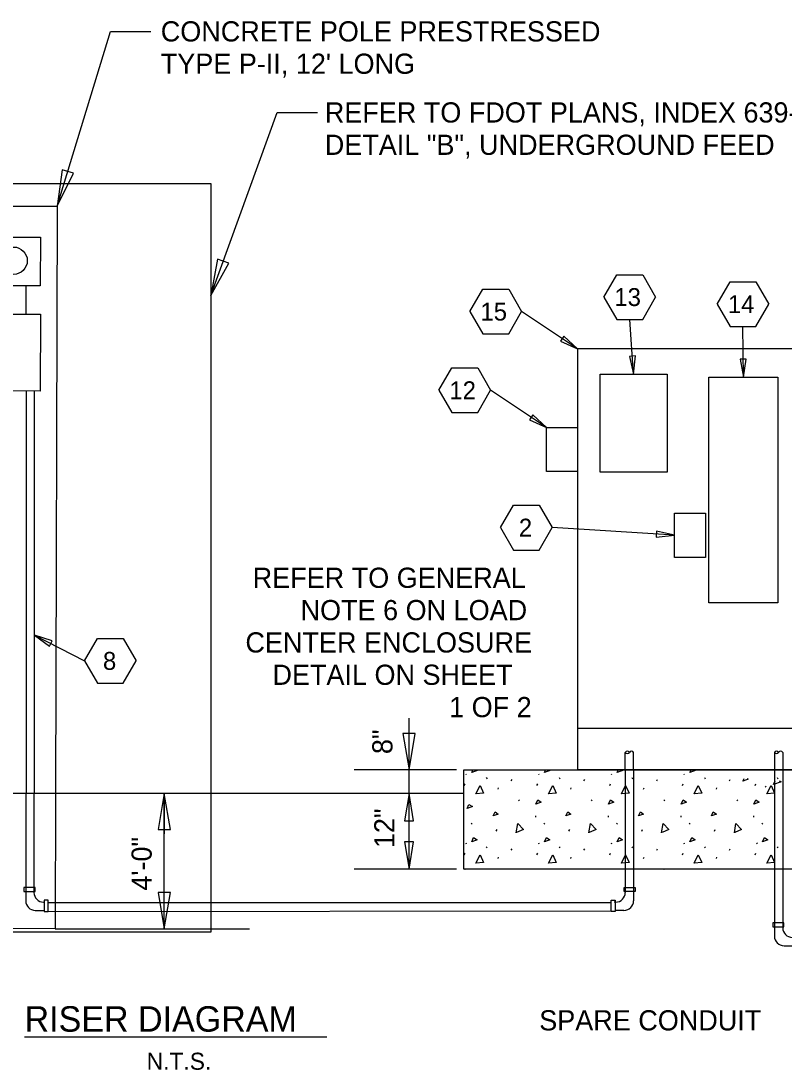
# Model space of a CAD drawing. Extents: x 359576 to 360896, y 1607020 to 1607868.
# Drawn here: x 360503.5 to 360730.2, y 1607389.8 to 1607701.3 of the extents above; entities that cross this region are included whole.
import ezdxf

# ---------------------------------------------------------------- set-up
doc = ezdxf.new("R2010")
doc.units = 0
doc.layers.add('Default', color=7, linetype='Continuous')
doc.layers.add('LaneLine_ep', color=7, linetype='Continuous')

msp = doc.modelspace()

# ---------------------------------------------------------------- linework, layer by layer
at = {"layer": 'Default'}
for p, q in [((360489.42, 1607646.37), (360514.17, 1607646.3)), ((360514.24, 1607646.3), (360513.74, 1607471.93)), ((360676.67, 1607619.32), (360680.5, 1607625.95)), ((360680.5, 1607625.95), (360688.17, 1607625.95)), ((360688.17, 1607625.95), (360692, 1607619.32)), ((360505.03, 1607614.28), (360505.03, 1607622.63)), ((360636.85, 1607615), (360640.68, 1607621.64)), ((360640.68, 1607621.64), (360648.35, 1607621.64)), ((360648.35, 1607621.64), (360652.18, 1607615)), ((360710.28, 1607617.2), (360714.12, 1607623.84)), ((360714.12, 1607623.84), (360721.78, 1607623.84)), ((360721.78, 1607623.84), (360725.62, 1607617.2)), ((360676.67, 1607619.32), (360680.5, 1607612.68)), ((360688.17, 1607612.68), (360692, 1607619.32)), ((360636.85, 1607615), (360640.68, 1607608.36)), ((360648.35, 1607608.36), (360652.18, 1607615)), ((360710.28, 1607617.2), (360714.12, 1607610.56)), ((360721.78, 1607610.56), (360725.62, 1607617.2)), ((360680.5, 1607612.68), (360688.17, 1607612.68)), ((360640.68, 1607608.36), (360648.35, 1607608.36)), ((360714.12, 1607610.56), (360721.78, 1607610.56)), ((360627.65, 1607591.64), (360631.48, 1607598.28)), ((360631.48, 1607598.28), (360639.15, 1607598.28)), ((360639.15, 1607598.28), (360642.98, 1607591.64)), ((360504.95, 1607591.34), (360504.95, 1607471.95)), ((360507.41, 1607591.41), (360507.41, 1607471.95)), ((360627.65, 1607591.64), (360631.48, 1607585)), ((360639.15, 1607585), (360642.98, 1607591.64)), ((360631.48, 1607585), (360639.15, 1607585)), ((360645.91, 1607550.85), (360649.74, 1607557.49)), ((360649.74, 1607557.49), (360657.41, 1607557.49)), ((360657.41, 1607557.49), (360661.24, 1607550.85)), ((360645.91, 1607550.85), (360649.74, 1607544.21)), ((360657.41, 1607544.21), (360661.24, 1607550.85)), ((360649.74, 1607544.21), (360657.41, 1607544.21)), ((360522.32, 1607511.27), (360526.16, 1607517.91)), ((360526.16, 1607517.91), (360533.82, 1607517.91)), ((360533.82, 1607517.91), (360537.65, 1607511.27)), ((360522.32, 1607511.27), (360526.16, 1607504.63)), ((360533.82, 1607504.63), (360537.65, 1607511.27)), ((360526.16, 1607504.63), (360533.82, 1607504.63)), ((360668.76, 1607491.27), (360773.13, 1607491.27)), ((360682.99, 1607479), (360682.99, 1607484.1)), ((360685.45, 1607478.99), (360685.45, 1607484.1)), ((360727.31, 1607484.1), (360727.31, 1607429.57)), ((360729.77, 1607484.1), (360729.77, 1607432.03)), ((360635.06, 1607449.39), (360635.06, 1607478.91)), ((360635.06, 1607478.91), (360795.13, 1607478.91)), ((360635.61, 1607477.79), (360635.72, 1607477.56)), ((360657.21, 1607477.79), (360657.32, 1607477.56)), ((360678.81, 1607477.79), (360678.93, 1607477.56)), ((360682.99, 1607479), (360682.99, 1607442.5)), ((360685.45, 1607478.99), (360685.45, 1607440.04)), ((360700.41, 1607477.79), (360700.53, 1607477.56)), ((360635.15, 1607474.31), (360635.38, 1607474.77)), ((360641.7, 1607476.65), (360641.93, 1607476.31)), ((360649.11, 1607475.62), (360649.34, 1607476.08)), ((360656.75, 1607474.31), (360656.98, 1607474.77)), ((360663.31, 1607476.65), (360663.54, 1607476.31)), ((360670.72, 1607475.62), (360670.95, 1607476.08)), ((360678.36, 1607474.31), (360678.58, 1607474.77)), ((360684.91, 1607476.65), (360685.14, 1607476.31)), ((360692.32, 1607475.62), (360692.55, 1607476.08)), ((360699.96, 1607474.31), (360700.19, 1607474.77)), ((360706.51, 1607476.65), (360706.74, 1607476.31)), ((360713.92, 1607475.62), (360714.15, 1607476.08)), ((360721.56, 1607474.31), (360721.79, 1607474.77)), ((360728.12, 1607476.65), (360728.34, 1607476.31)), ((360635.06, 1607471.95), (360329.76, 1607471.95)), ((360504.86, 1607471.95), (360504.86, 1607440.04)), ((360507.32, 1607471.95), (360507.32, 1607442.5)), ((360645.24, 1607473.17), (360645.35, 1607473.63)), ((360666.84, 1607473.17), (360666.96, 1607473.63)), ((360688.44, 1607473.17), (360688.56, 1607473.63)), ((360710.05, 1607473.17), (360710.16, 1607473.63)), ((360724.57, 1607474.12), (360724.73, 1607473.8)), ((360651.28, 1607469.98), (360651.51, 1607469.75)), ((360672.88, 1607469.98), (360673.11, 1607469.75)), ((360694.49, 1607469.98), (360694.71, 1607469.75)), ((360716.09, 1607469.98), (360716.32, 1607469.75)), ((360656.3, 1607465.31), (360656.3, 1607464.85)), ((360677.9, 1607465.31), (360677.9, 1607464.85)), ((360699.5, 1607465.31), (360699.5, 1607464.85)), ((360721.11, 1607465.31), (360721.11, 1607464.85)), ((360637.26, 1607462.8), (360637.49, 1607463.14)), ((360658.86, 1607462.8), (360659.09, 1607463.14)), ((360680.46, 1607462.8), (360680.69, 1607463.14)), ((360702.07, 1607462.8), (360702.3, 1607463.14)), ((360723.67, 1607462.8), (360723.9, 1607463.14)), ((360644.67, 1607460.75), (360644.9, 1607461.2)), ((360666.27, 1607460.75), (360666.5, 1607461.2)), ((360687.87, 1607460.75), (360688.1, 1607461.2)), ((360709.48, 1607460.75), (360709.71, 1607461.2)), ((360635.61, 1607457.21), (360635.72, 1607456.98)), ((360641.7, 1607456.07), (360641.93, 1607455.73)), ((360657.21, 1607457.21), (360657.32, 1607456.98)), ((360663.31, 1607456.07), (360663.54, 1607455.73)), ((360678.81, 1607457.21), (360678.93, 1607456.98)), ((360684.91, 1607456.07), (360685.14, 1607455.73)), ((360700.41, 1607457.21), (360700.53, 1607456.98)), ((360706.51, 1607456.07), (360706.74, 1607455.73)), ((360722.02, 1607457.21), (360722.13, 1607456.98)), ((360728.12, 1607456.07), (360728.34, 1607455.73)), ((360635.15, 1607453.73), (360635.38, 1607454.19)), ((360645.24, 1607452.59), (360645.35, 1607453.05)), ((360649.11, 1607455.05), (360649.34, 1607455.5)), ((360656.75, 1607453.73), (360656.98, 1607454.19)), ((360666.84, 1607452.59), (360666.96, 1607453.05)), ((360670.72, 1607455.05), (360670.95, 1607455.5)), ((360678.36, 1607453.73), (360678.58, 1607454.19)), ((360688.44, 1607452.59), (360688.56, 1607453.05)), ((360692.32, 1607455.05), (360692.55, 1607455.5)), ((360699.96, 1607453.73), (360700.19, 1607454.19)), ((360710.05, 1607452.59), (360710.16, 1607453.05)), ((360713.92, 1607455.05), (360714.15, 1607455.5)), ((360721.56, 1607453.73), (360721.79, 1607454.19)), ((360795.13, 1607449.39), (360635.06, 1607449.39)), ((360651.28, 1607449.4), (360651.29, 1607449.39)), ((360672.88, 1607449.4), (360672.89, 1607449.39)), ((360694.49, 1607449.4), (360694.5, 1607449.39)), ((360716.09, 1607449.4), (360716.1, 1607449.39)), ((360507.71, 1607437.19), (360510.32, 1607437.19)), ((360511.49, 1607439.51), (360678.83, 1607439.51)), ((360511.49, 1607436.9), (360678.83, 1607437.04)), ((360680.14, 1607439.65), (360679.72, 1607439.65)), ((360682.6, 1607437.19), (360679.99, 1607437.19)), ((360730.16, 1607426.72), (360732.77, 1607426.72)), ((360504.52, 1607399.66), (360594.31, 1607399.66))]:
    msp.add_line(p, q, dxfattribs=at)
for points in [[(360448.79, 1607653.09), (360559.9, 1607653.09), (360559.9, 1607430.72), (360448.79, 1607430.72)], [(360493.19, 1607637.12), (360509.24, 1607637.07), (360509.2, 1607622.62), (360493.15, 1607622.67)], [(360493.19, 1607614.29), (360509.24, 1607614.24), (360509.18, 1607591.41), (360493.13, 1607591.45)], [(360773.13, 1607603.99), (360668.76, 1607603.99), (360668.76, 1607478.99), (360773.13, 1607478.99)], [(360675.54, 1607596.4), (360695.42, 1607596.4), (360695.42, 1607567.32), (360675.54, 1607567.32)], [(360707.8, 1607595.52), (360728.36, 1607595.52), (360728.36, 1607528.53), (360707.8, 1607528.53)], [(360668.76, 1607580.63), (360668.76, 1607567.51), (360659.56, 1607567.51), (360659.56, 1607580.63)], [(360706.82, 1607555.15), (360706.82, 1607542.03), (360697.62, 1607542.03), (360697.62, 1607555.15)], [(360507.69, 1607442.82), (360507.69, 1607443.99), (360504.34, 1607443.99), (360504.34, 1607442.82)], [(360682.62, 1607442.82), (360682.62, 1607443.99), (360685.97, 1607443.99), (360685.97, 1607442.82)], [(360511.49, 1607440.24), (360510.32, 1607440.24), (360510.32, 1607436.9), (360511.49, 1607436.9)], [(360678.83, 1607440.24), (360679.99, 1607440.24), (360679.99, 1607436.9), (360678.83, 1607436.9)], [(360730.14, 1607432.35), (360730.14, 1607433.52), (360726.79, 1607433.52), (360726.79, 1607432.35)]]:
    msp.add_lwpolyline(points, close=True, dxfattribs=at)
for points in [[(360638.66, 1607478.91), (360638.97, 1607478.7), (360637.37, 1607478.13)], [(360637.37, 1607478.13), (360637.73, 1607478.91)], [(360660.26, 1607478.91), (360660.57, 1607478.7), (360658.98, 1607478.13)], [(360658.98, 1607478.13), (360659.33, 1607478.91)], [(360681.86, 1607478.91), (360682.17, 1607478.7), (360680.58, 1607478.13)], [(360680.58, 1607478.13), (360680.93, 1607478.91)], [(360703.47, 1607478.91), (360703.78, 1607478.7), (360702.18, 1607478.13)], [(360702.18, 1607478.13), (360702.53, 1607478.91)], [(360719.23, 1607476.35), (360719.54, 1607476.15), (360717.95, 1607475.58)], [(360717.95, 1607475.58), (360718.3, 1607476.35)], [(360728.84, 1607475.69), (360729.28, 1607475.4), (360727.04, 1607474.6)], [(360727.04, 1607474.6), (360727.54, 1607475.69)], [(360513.74, 1607471.93), (360513.62, 1607431.72), (360488.88, 1607431.79), (360489, 1607471.96)], [(360638.63, 1607471.8), (360639.88, 1607474.31), (360640.91, 1607472.03), (360638.63, 1607471.8)], [(360660.23, 1607471.8), (360661.48, 1607474.31), (360662.51, 1607472.03), (360660.23, 1607471.8)], [(360681.83, 1607471.8), (360683.09, 1607474.31), (360684.11, 1607472.03), (360681.83, 1607471.8)], [(360703.44, 1607471.8), (360704.69, 1607474.31), (360705.72, 1607472.03), (360703.44, 1607471.8)], [(360725.04, 1607471.8), (360726.29, 1607474.31), (360727.32, 1607472.03), (360725.04, 1607471.8)], [(360635.98, 1607467.44), (360636.55, 1607468.69), (360637.57, 1607468.01), (360635.98, 1607467.44)], [(360656.41, 1607468.73), (360656.98, 1607469.98), (360658.01, 1607469.3), (360656.41, 1607468.73)], [(360678.01, 1607468.73), (360678.58, 1607469.98), (360679.61, 1607469.3), (360678.01, 1607468.73)], [(360699.62, 1607468.73), (360700.19, 1607469.98), (360701.21, 1607469.3), (360699.62, 1607468.73)], [(360721.22, 1607468.73), (360721.79, 1607469.98), (360722.82, 1607469.3), (360721.22, 1607468.73)], [(360643.76, 1607465.31), (360644.33, 1607466.45), (360645.24, 1607465.76), (360643.76, 1607465.31)], [(360665.36, 1607465.31), (360665.93, 1607466.45), (360666.84, 1607465.76), (360665.36, 1607465.31)], [(360686.96, 1607465.31), (360687.53, 1607466.45), (360688.44, 1607465.76), (360686.96, 1607465.31)], [(360708.57, 1607465.31), (360709.14, 1607466.45), (360710.05, 1607465.76), (360708.57, 1607465.31)], [(360650.6, 1607460.18), (360651.05, 1607463.03), (360652.76, 1607461.2), (360650.71, 1607460.29)], [(360672.2, 1607460.18), (360672.66, 1607463.03), (360674.37, 1607461.2), (360672.31, 1607460.29)], [(360693.8, 1607460.18), (360694.26, 1607463.03), (360695.97, 1607461.2), (360693.92, 1607460.29)], [(360715.41, 1607460.18), (360715.86, 1607463.03), (360717.57, 1607461.2), (360715.52, 1607460.29)], [(360637.37, 1607457.55), (360637.94, 1607458.81), (360638.97, 1607458.12), (360637.37, 1607457.55)], [(360658.98, 1607457.55), (360659.55, 1607458.81), (360660.57, 1607458.12), (360658.98, 1607457.55)], [(360680.58, 1607457.55), (360681.15, 1607458.81), (360682.17, 1607458.12), (360680.58, 1607457.55)], [(360702.18, 1607457.55), (360702.75, 1607458.81), (360703.78, 1607458.12), (360702.18, 1607457.55)], [(360723.78, 1607457.55), (360724.35, 1607458.81), (360725.38, 1607458.12), (360723.78, 1607457.55)], [(360638.63, 1607451.23), (360639.88, 1607453.73), (360640.91, 1607451.45), (360638.63, 1607451.23)], [(360660.23, 1607451.23), (360661.48, 1607453.73), (360662.51, 1607451.45), (360660.23, 1607451.23)], [(360681.83, 1607451.23), (360683.09, 1607453.73), (360684.11, 1607451.45), (360681.83, 1607451.23)], [(360703.44, 1607451.23), (360704.69, 1607453.73), (360705.72, 1607451.45), (360703.44, 1607451.23)], [(360725.04, 1607451.23), (360726.29, 1607453.73), (360727.32, 1607451.45), (360725.04, 1607451.23)], [(360635.37, 1607449.39), (360635.38, 1607449.4), (360635.39, 1607449.39)], [(360656.98, 1607449.39), (360656.98, 1607449.4), (360656.99, 1607449.39)], [(360678.58, 1607449.39), (360678.58, 1607449.4), (360678.6, 1607449.39)], [(360700.18, 1607449.39), (360700.19, 1607449.4), (360700.2, 1607449.39)], [(360721.79, 1607449.39), (360721.79, 1607449.4), (360721.8, 1607449.39)]]:
    msp.add_lwpolyline(points, dxfattribs=at)
msp.add_circle((360501.27, 1607630.13), 4.06, dxfattribs=at)
for centre, radius, start, end in [((360683.61, 1607483.75), 0.708, 29.4643, 150.5357), ((360683.61, 1607484.45), 0.708, 209.4643, 330.5357), ((360684.84, 1607483.75), 0.708, 29.4643, 150.5357), ((360727.93, 1607483.75), 0.708, 29.4643, 150.5357), ((360727.93, 1607484.45), 0.708, 209.4643, 330.5357), ((360729.16, 1607483.75), 0.708, 29.4643, 150.5357), ((360510.17, 1607442.5), 2.85, 180, 270), ((360680.14, 1607442.5), 2.85, 270, 360), ((360507.71, 1607440.04), 2.85, 180, 270), ((360682.6, 1607440.04), 2.85, 270, 360), ((360732.62, 1607432.03), 2.85, 180, 270), ((360730.16, 1607429.57), 2.85, 180, 270)]:
    msp.add_arc(centre, radius, start, end, dxfattribs=at)
at = {"layer": 'LaneLine_ep'}
for p, q in [((360697.62, 1607548.59), (360661.24, 1607550.85)), ((360632.87, 1607478.91), (360602.43, 1607478.91)), ((360618.74, 1607471.95), (360618.74, 1607478.91)), ((360632.87, 1607449.39), (360602.43, 1607449.39)), ((360513.62, 1607431.72), (360549.46, 1607431.72)), ((360513.62, 1607431.72), (360571.39, 1607431.72)), ((360531.54, 1607431.72), (360550.97, 1607431.72))]:
    msp.add_line(p, q, dxfattribs=at)
for points in [[(360514.24, 1607646.3), (360530.07, 1607698.22), (360542.05, 1607698.22)], [(360559.87, 1607619.83), (360579.53, 1607674.15), (360591.51, 1607674.15)], [(360668.76, 1607603.99), (360652.18, 1607615)], [(360685.48, 1607596.4), (360684.34, 1607612.68)], [(360718.08, 1607595.52), (360717.95, 1607610.56)], [(360659.56, 1607580.63), (360642.98, 1607591.64)], [(360507.5, 1607518.88), (360522.32, 1607511.27)], [(360618.74, 1607478.91), (360618.74, 1607494.29)], [(360546.03, 1607431.72), (360546.03, 1607471.95)], [(360546.03, 1607471.95), (360546.03, 1607459.97)], [(360618.74, 1607449.39), (360618.74, 1607471.95)]]:
    msp.add_lwpolyline(points, dxfattribs=at)
for points in [[(360515.67, 1607657.14), (360514.24, 1607646.3), (360519.1, 1607656.09)], [(360561.85, 1607630.58), (360559.87, 1607619.83), (360565.23, 1607629.36)], [(360663.77, 1607606.23), (360668.76, 1607603.99), (360664.76, 1607607.73)], [(360684.21, 1607601.72), (360685.48, 1607596.4), (360686, 1607601.85)], [(360717.13, 1607600.91), (360718.08, 1607595.52), (360718.93, 1607600.93)], [(360654.56, 1607582.86), (360659.56, 1607580.63), (360655.56, 1607584.36)], [(360692.17, 1607548.03), (360697.62, 1607548.59), (360692.29, 1607549.83)], [(360512.72, 1607517.22), (360507.5, 1607518.88), (360511.89, 1607515.62)], [(360616.95, 1607489.69), (360618.74, 1607478.91), (360620.54, 1607489.69)], [(360547.83, 1607461.17), (360546.03, 1607471.95), (360544.23, 1607461.17)], [(360620.11, 1607463.76), (360618.74, 1607471.95), (360617.38, 1607463.76)], [(360617.38, 1607457.59), (360618.74, 1607449.39), (360620.11, 1607457.59)], [(360544.23, 1607442.5), (360546.03, 1607431.72), (360547.83, 1607442.5)]]:
    msp.add_lwpolyline(points, close=True, dxfattribs=at)

# ---------------------------------------------------------------- texts
at = {"layer": 'Default'}
for s, p in [('CONCRETE POLE PRESTRESSED', (360544.99, 1607695.22)), ("TYPE P-II, 12' LONG", (360544.99, 1607685.62)), ('REFER TO FDOT PLANS, INDEX 639-001', (360593.72, 1607671.15)), ('DETAIL "B", UNDERGROUND FEED', (360593.72, 1607661.55))]:
    msp.add_text(s, height=6, dxfattribs=at).set_placement(p)
for s, height, rotation, p in [('13', 5.311, 360, (360679.75, 1607616.67)), ('15', 5.311, 360, (360639.96, 1607612.35)), ('14', 5.311, 360, (360713.48, 1607614.55)), ('12', 5.311, 360, (360630.73, 1607588.99)), ('2', 5.31, 360, (360651.38, 1607548.2)), ('REFER TO GENERAL', 6, 0, (360572.29, 1607532.97)), ('NOTE 6 ON LOAD', 6, 0, (360586.52, 1607523.37)), ('CENTER ENCLOSURE', 6, 0, (360570.14, 1607513.77)), ('8', 5.31, 360, (360527.81, 1607508.63)), ('DETAIL ON SHEET', 6, 0, (360578.17, 1607504.17)), ('1 OF 2', 6, 0, (360630.66, 1607494.57)), ('8"', 5.99, 90, (360613.82, 1607483.62)), ('12"', 5.99, 90, (360614.4, 1607455.7)), ('4\'-0"', 5.99, 90, (360542.29, 1607443.05)), ('RISER DIAGRAM', 7.5612, 360, (360504.52, 1607401.18)), ('SPARE CONDUIT', 6, 0, (360657.43, 1607401.55)), ('N.T.S.', 5.066, 360, (360540.8, 1607389.87))]:
    msp.add_text(s, height=height, rotation=rotation, dxfattribs=at).set_placement(p)

doc.saveas('drawing.dxf')
